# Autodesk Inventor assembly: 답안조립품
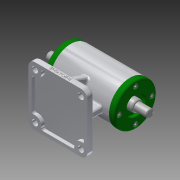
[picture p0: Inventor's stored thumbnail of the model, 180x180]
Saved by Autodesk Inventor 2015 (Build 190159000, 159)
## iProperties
Created: 2019-06
Part Number: 답안조립품
Document SubType Name: Assembly
Designer: a3
Author: a3
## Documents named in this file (7)
- C:\Users\a3\Desktop\490604V1015\답안조립품.iam
- C:\Users\a3\Desktop\490604V1015\본체.ipt
- C:\Users\a3\Desktop\490604V1015\베어링 6203.ipt
- C:\Users\a3\Desktop\490604V1015\축.ipt
- C:\Users\a3\Desktop\490604V1015\커버.ipt
- C:\Users\a3\Desktop\490604V1015\볼트 M4.ipt
- C:\Users\a3\Desktop\490604V1015\키 4x4x12.ipt
